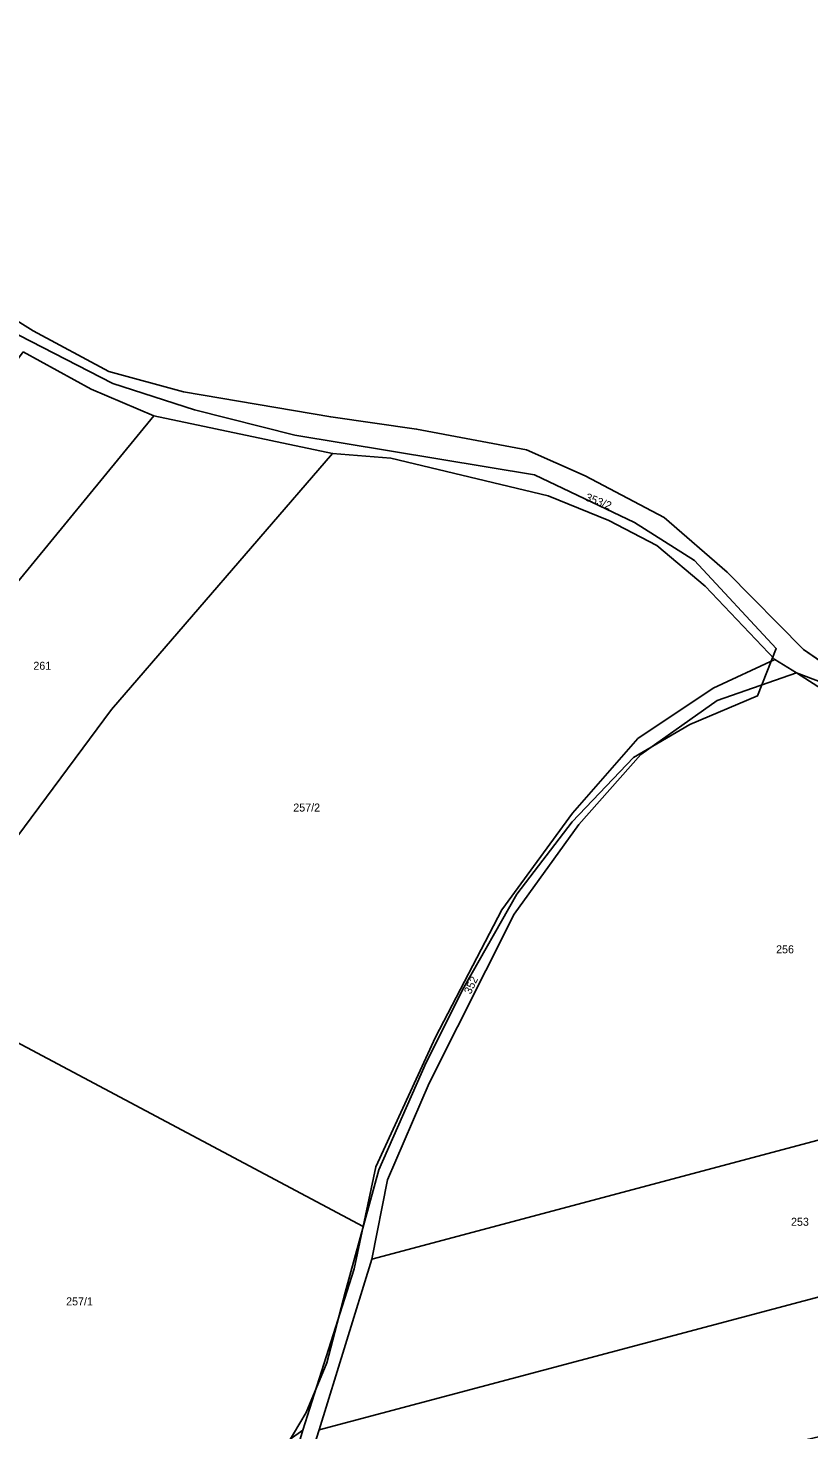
# Model space of a CAD drawing. Extents: x -590606 to -587796, y -1065936 to -1062515.
# Drawn here: x -588916 to -588750.2, y -1064752.6 to -1064454.8 of the extents above; entities that cross this region are included whole.
import ezdxf

# ---------------------------------------------------------------- set-up
doc = ezdxf.new("R2010")
doc.units = 0
for name, color, linetype in [('Cesty', 7, 'Continuous'), ('Parcela nároku', 7, 'Continuous'), ('Vnější obvod_ Studené', 7, 'Continuous')]:
    doc.layers.add(name, color=color, linetype=linetype)

msp = doc.modelspace()

# ---------------------------------------------------------------- linework, layer by layer
at = {"layer": 'Cesty'}
msp.add_lwpolyline([(-588861.03, -1064755.65), (-588857.02, -1064748.84), (-588852.59, -1064738.3), (-588848.73, -1064723.38), (-588841.54, -1064697.32), (-588831.49, -1064674.52), (-588823.5, -1064658.61), (-588812.25, -1064638.75), (-588800.52, -1064623.35), (-588787.51, -1064609.72), (-588775.51, -1064602.7), (-588761.19, -1064596.65), (-588757.18, -1064586.53), (-588774.55, -1064567.84), (-588787.29, -1064559.81), (-588808.51, -1064549.7), (-588859.37, -1064541.23), (-588880.72, -1064535.83), (-588898.07, -1064530.25), (-588930.49, -1064513.65)], dxfattribs=at)
at = {"layer": 'Parcela nároku'}
for points in [[(-588733.73, -1064598.99), (-588751.39, -1064586.78), (-588767.59, -1064570.33), (-588781, -1064558.75), (-588797.78, -1064549.89), (-588810.19, -1064544.34), (-588833.56, -1064539.94), (-588851.76, -1064537.38), (-588883.06, -1064532.07), (-588898.92, -1064527.72), (-588914.98, -1064519.09), (-588929.76, -1064509.87), (-588945.38, -1064498.45), (-588946.89, -1064494.75), (-588949.94, -1064487.27), (-588944.74, -1064481.83), (-588953.65, -1064468.8), (-588966.43, -1064457.09), (-588932.01, -1064450.94)], [(-588917.11, -1064523.51), (-588902.66, -1064531.5), (-588889.35, -1064537.12), (-588851.4, -1064545.12), (-588839.04, -1064546.13), (-588805.58, -1064554.11), (-588792.71, -1064559.39), (-588782.54, -1064564.66), (-588772.3, -1064573.34), (-588757.48, -1064588.92), (-588752.85, -1064591.76), (-588733.73, -1064598.99), (-588751.39, -1064586.78), (-588767.59, -1064570.33), (-588781, -1064558.75), (-588797.78, -1064549.89), (-588810.19, -1064544.34), (-588833.56, -1064539.94), (-588851.76, -1064537.38), (-588883.06, -1064532.07), (-588898.92, -1064527.72), (-588914.98, -1064519.09), (-588929.76, -1064509.87)]]:
    msp.add_lwpolyline(points, dxfattribs=at)
for points in [[(-588917.11, -1064523.51), (-588902.66, -1064531.5), (-588889.35, -1064537.12), (-588921.82, -1064576.81), (-588953.26, -1064619.99), (-588956.87, -1064624.68), (-588975.18, -1064601.25)], [(-588921.82, -1064576.81), (-588889.35, -1064537.12), (-588851.4, -1064545.12), (-588898.31, -1064599.49), (-588941.62, -1064657.84), (-588953.26, -1064619.99)], [(-588851.4, -1064545.12), (-588839.04, -1064546.13), (-588805.58, -1064554.11), (-588792.71, -1064559.39), (-588782.54, -1064564.66), (-588772.3, -1064573.34), (-588757.48, -1064588.92), (-588770.58, -1064594.99), (-588786.57, -1064605.7), (-588800.43, -1064621.56), (-588815.43, -1064642.06), (-588829.52, -1064669.09), (-588842.19, -1064696.66), (-588844.89, -1064709.35), (-588941.62, -1064657.84), (-588898.31, -1064599.49)], [(-588846.83, -1064718.35), (-588844.89, -1064709.35), (-588842.19, -1064696.66), (-588829.52, -1064669.09), (-588815.43, -1064642.06), (-588800.43, -1064621.56), (-588786.57, -1064605.7), (-588770.58, -1064594.99), (-588757.48, -1064588.92), (-588752.85, -1064591.76), (-588769.73, -1064597.63), (-588785.94, -1064609.09), (-588799.1, -1064623.95), (-588812.84, -1064642.98), (-588830.89, -1064678.89), (-588839.7, -1064699.44), (-588843.04, -1064716.27), (-588854.26, -1064752.55), (-588855.4, -1064756.26), (-588859.45, -1064758.58), (-588857.69, -1064752.58)], [(-588752.85, -1064591.76), (-588769.73, -1064597.63), (-588785.94, -1064609.09), (-588799.1, -1064623.95), (-588812.84, -1064642.98), (-588830.89, -1064678.89), (-588839.7, -1064699.44), (-588843.04, -1064716.27), (-588725.99, -1064685.06), (-588661.44, -1064673.09), (-588686.75, -1064636.98), (-588713.94, -1064612.69), (-588727.09, -1064608.26)], [(-588656.17, -1064672.2), (-588683.4, -1064632.89), (-588711.57, -1064608.36), (-588728.1, -1064601.91), (-588733.73, -1064598.99), (-588752.85, -1064591.76), (-588727.09, -1064608.26), (-588713.94, -1064612.69), (-588686.75, -1064636.98), (-588661.44, -1064673.09)], [(-588952.5, -1064671.53), (-588941.62, -1064657.84), (-588844.89, -1064709.35), (-588846.83, -1064718.35), (-588857.69, -1064752.58), (-588892.68, -1064777.43), (-588925.79, -1064796.63), (-588930.91, -1064779.48), (-588944.46, -1064764.13), (-588949.37, -1064743.17), (-588950.66, -1064722.17), (-588946.87, -1064713.5), (-588956.12, -1064688.59)], [(-588725.99, -1064685.06), (-588843.04, -1064716.27), (-588854.26, -1064752.55), (-588723.57, -1064717.79), (-588654.07, -1064706.04), (-588652.87, -1064689.03), (-588661.44, -1064673.09)], [(-588723.57, -1064717.79), (-588854.26, -1064752.55), (-588855.4, -1064756.26), (-588863.82, -1064785.09), (-588834.74, -1064778.58), (-588793.39, -1064764.73), (-588709.36, -1064744.84), (-588674.26, -1064739.84), (-588657.16, -1064739.85), (-588654.7, -1064731.53), (-588654.07, -1064706.04)]]:
    msp.add_lwpolyline(points, close=True, dxfattribs=at)
at = {"layer": 'Vnější obvod_ Studené'}
for p, q in [((-588914.98, -1064519.09), (-588929.76, -1064509.87)), ((-588898.92, -1064527.72), (-588914.98, -1064519.09)), ((-588883.06, -1064532.07), (-588898.92, -1064527.72)), ((-588851.76, -1064537.38), (-588883.06, -1064532.07)), ((-588833.56, -1064539.94), (-588851.76, -1064537.38)), ((-588810.19, -1064544.34), (-588833.56, -1064539.94)), ((-588797.78, -1064549.89), (-588810.19, -1064544.34)), ((-588781, -1064558.75), (-588797.78, -1064549.89)), ((-588767.59, -1064570.33), (-588781, -1064558.75)), ((-588751.39, -1064586.78), (-588767.59, -1064570.33)), ((-588733.73, -1064598.99), (-588751.39, -1064586.78))]:
    msp.add_line(p, q, dxfattribs=at)

# ---------------------------------------------------------------- texts
at = {"layer": 'Parcela nároku'}
for s, rotation, p in [('353/2', 338.933, (-588797.86, -1064555.08)), ('352', 64.7564, (-588822.05, -1064660.14))]:
    msp.add_text(s, height=1.7, rotation=rotation, dxfattribs=at).set_placement(p)
for s, p in [('261', (-588914.92, -1064591.08)), ('257/2', (-588859.73, -1064621.2)), ('256', (-588757.21, -1064651.31)), ('253', (-588754.04, -1064709.19)), ('257/1', (-588907.96, -1064726.1))]:
    msp.add_text(s, height=1.7, dxfattribs=at).set_placement(p)

doc.saveas('drawing.dxf')
